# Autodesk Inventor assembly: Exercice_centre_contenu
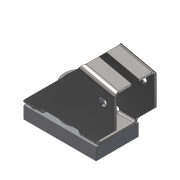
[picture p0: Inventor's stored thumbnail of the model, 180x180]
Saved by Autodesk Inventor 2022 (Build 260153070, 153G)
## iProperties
Created: 2018-06
Part Number: Exercice_centre_contenu
Material: Générique
Document SubType Name: Assembly
Designer: Fabian Perrée
Mass: 105.136 g
Surface Area: 173.547 cm^2
Volume: 19.7524 cm^3
Density: 5.32267 g/cm^3
Author: Fabian Perrée
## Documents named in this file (4)
- C:\Users\Fabian\Google Drive\01_Giup\01_Clients\07_ENI\Manuscrit\Fichiers_exercice\Chapitre_06\Exercice_Centre_contenu\Exercice_centre_contenu.iam
- C:\Users\Fabian\Google Drive\01_Giup\01_Clients\07_ENI\Manuscrit\Fichiers_exercice\Chapitre_06\Exercice_Centre_contenu\Composants\Etrier_tole.ipt
- C:\Users\Fabian\Google Drive\01_Giup\01_Clients\07_ENI\Manuscrit\Fichiers_exercice\Chapitre_06\Exercice_Centre_contenu\Composants\Chapeau_capteur.ipt
- C:\Users\Fabian\Google Drive\01_Giup\01_Clients\07_ENI\Manuscrit\Fichiers_exercice\Chapitre_06\Exercice_Centre_contenu\Composants\Bille_18.ipt
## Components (3 placed, 3 different names)
1. Etrier_tole:1 — Logement:3, Logement:4
2. Chapeau_capteur:1 — Logement:3, Logement:4
3. Bille_18:1
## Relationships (2: Insert 2)
- Logement:3 [Insert]: Etrier_tole:1 ↔ Chapeau_capteur:1
- Logement:4 [Insert]: Etrier_tole:1 ↔ Chapeau_capteur:1
